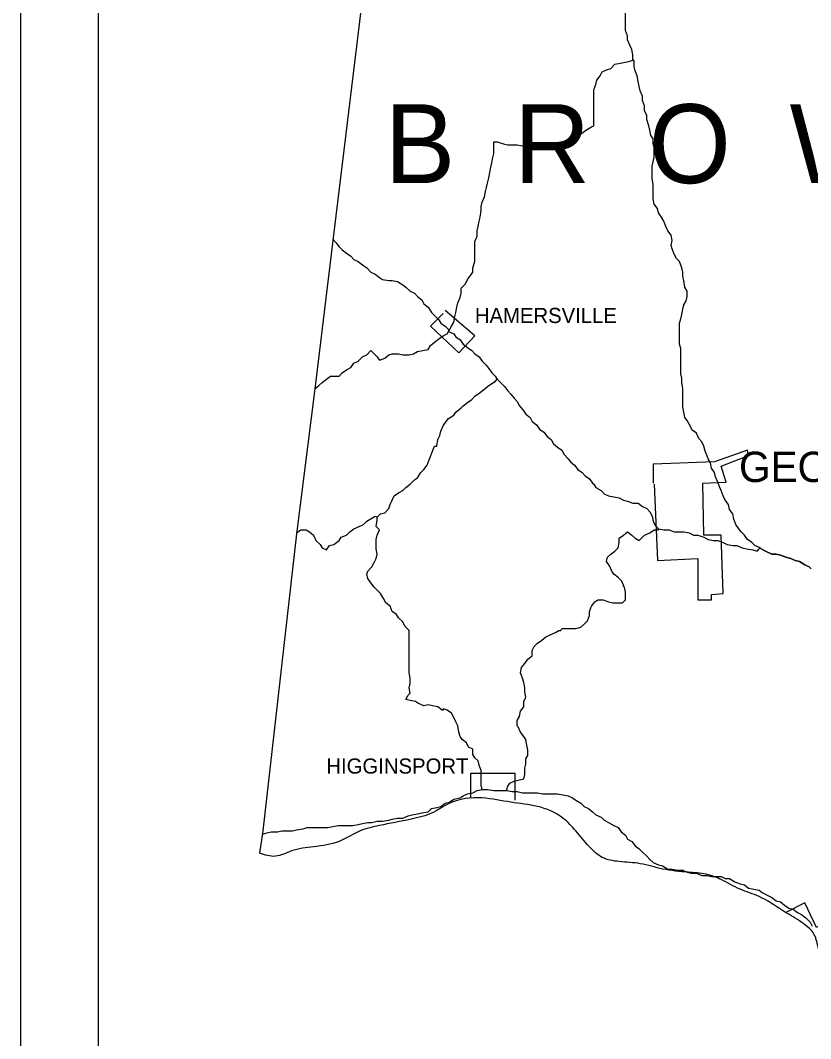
# Model space of a CAD drawing. Extents: x 0 to 34, y 0 to 22.
# Drawn here: x 2 to 3.016, y 16.334 to 17.643 of the extents above; entities that cross this region are included whole.
import ezdxf

# ---------------------------------------------------------------- set-up
doc = ezdxf.new("R2010")
doc.units = 0
for name, color, linetype in [('Default', 7, 'Continuous'), ('SH_Data', 7, 'Continuous'), ('TR_Turning_Path1', 7, 'Continuous')]:
    doc.layers.add(name, color=color, linetype=linetype)

msp = doc.modelspace()

# ---------------------------------------------------------------- linework, layer by layer
at = {"layer": 'Default'}
for points in [[(2.5542, 18.7551), (2.546, 18.6256), (2.5378, 18.5029), (2.5255, 18.387), (2.5105, 18.2684), (2.5078, 18.2343), (2.4914, 18.0952), (2.4737, 17.9548), (2.456, 17.8075), (2.4014, 17.3603), (2.3783, 17.1694), (2.3551, 16.9827), (2.3115, 16.6009), (2.3074, 16.5723)], [(2.7873, 17.5935), (2.7873, 17.5989), (2.7859, 17.6057), (2.7832, 17.6112), (2.7805, 17.618), (2.7805, 17.6235), (2.7778, 17.6303), (2.7778, 17.6371), (2.7778, 17.6439), (2.7778, 17.6507), (2.7778, 17.6562), (2.7791, 17.663), (2.7805, 17.6685), (2.7805, 17.6753), (2.7805, 17.6835), (2.7805, 17.6889), (2.7805, 17.6957), (2.7859, 17.7012), (2.7887, 17.7066), (2.7928, 17.7121), (2.7955, 17.7175), (2.7968, 17.7244), (2.7968, 17.7244)], [(2.7369, 17.5089), (2.7369, 17.5158), (2.7369, 17.5212), (2.7369, 17.528), (2.7369, 17.5348), (2.7369, 17.5403), (2.7369, 17.5471), (2.7369, 17.5539), (2.7396, 17.5607), (2.7409, 17.5662), (2.745, 17.5717), (2.7478, 17.5771), (2.7532, 17.5798), (2.7587, 17.5812), (2.7641, 17.5867), (2.7709, 17.588), (2.7778, 17.5894), (2.7832, 17.5907), (2.7873, 17.5921), (2.7873, 17.5935)], [(2.8105, 17.4953), (2.8091, 17.5021), (2.8077, 17.5076), (2.805, 17.5158), (2.805, 17.5212), (2.8023, 17.5267), (2.8023, 17.5335), (2.7996, 17.5403), (2.7996, 17.5458), (2.7968, 17.5526), (2.7955, 17.558), (2.7941, 17.5648), (2.7928, 17.5717), (2.79, 17.5785), (2.7887, 17.5839), (2.7887, 17.5907), (2.7873, 17.5935)], [(2.6005, 17.4339), (2.6019, 17.4408), (2.6032, 17.4476), (2.6046, 17.4544), (2.606, 17.4599), (2.6073, 17.4667), (2.6087, 17.4721), (2.6087, 17.4789), (2.6087, 17.4871), (2.6128, 17.4871), (2.621, 17.4844), (2.6264, 17.483), (2.6319, 17.483), (2.6387, 17.483), (2.6455, 17.4817), (2.6523, 17.4803), (2.6578, 17.4803), (2.6646, 17.4803), (2.6714, 17.4789), (2.6769, 17.4776), (2.6823, 17.4803), (2.6891, 17.483), (2.6946, 17.4871), (2.7, 17.4885), (2.7069, 17.4898), (2.7123, 17.4912), (2.7178, 17.4953), (2.7232, 17.4994), (2.7287, 17.5035), (2.7341, 17.5062), (2.7369, 17.5076), (2.7369, 17.5089)], [(2.8118, 17.4421), (2.8118, 17.4476), (2.8118, 17.4558), (2.8132, 17.4612), (2.8146, 17.4667), (2.8146, 17.4721), (2.8146, 17.4803), (2.8132, 17.4844), (2.8132, 17.4912), (2.8105, 17.4953)], [(2.5501, 17.2431), (2.5542, 17.2499), (2.5569, 17.2553), (2.5582, 17.2622), (2.5596, 17.2676), (2.561, 17.2744), (2.5623, 17.2799), (2.5651, 17.2867), (2.5664, 17.2922), (2.5664, 17.299), (2.5719, 17.3044), (2.5746, 17.3099), (2.5787, 17.3153), (2.5814, 17.3194), (2.5814, 17.3249), (2.5841, 17.3331), (2.5841, 17.3399), (2.5841, 17.3453), (2.5841, 17.3521), (2.5841, 17.359), (2.5869, 17.3658), (2.5869, 17.3726), (2.5882, 17.378), (2.5896, 17.3849), (2.591, 17.3903), (2.5923, 17.3985), (2.5923, 17.404), (2.5937, 17.4094), (2.5964, 17.4162), (2.5978, 17.423), (2.5991, 17.4285), (2.6005, 17.4339), (2.6005, 17.4339)], [(2.8568, 17.2894), (2.8568, 17.2949), (2.8541, 17.3003), (2.8527, 17.3085), (2.8514, 17.314), (2.8514, 17.3194), (2.85, 17.3249), (2.8473, 17.3331), (2.8432, 17.3371), (2.8405, 17.3426), (2.8377, 17.3494), (2.8364, 17.3535), (2.8377, 17.3603), (2.8364, 17.3671), (2.8323, 17.3726), (2.8296, 17.378), (2.8268, 17.3849), (2.8241, 17.3903), (2.82, 17.3958), (2.8187, 17.4012), (2.8146, 17.4067), (2.8132, 17.4135), (2.8132, 17.4203), (2.8132, 17.4258), (2.8132, 17.4326), (2.8118, 17.4394), (2.8118, 17.4421), (2.8118, 17.4421)], [(2.4014, 17.3617), (2.4055, 17.3576), (2.4096, 17.3521), (2.4137, 17.3481), (2.4192, 17.344), (2.4246, 17.3399), (2.4287, 17.3358), (2.4342, 17.3331), (2.4396, 17.329), (2.4451, 17.3249), (2.4505, 17.3194), (2.456, 17.3167), (2.4614, 17.3126), (2.4655, 17.3099), (2.4737, 17.3085), (2.4778, 17.3085), (2.4846, 17.3072), (2.4914, 17.3031), (2.4955, 17.3003), (2.501, 17.2949), (2.5064, 17.2922), (2.5105, 17.2881), (2.516, 17.284), (2.5187, 17.2785), (2.5242, 17.2744), (2.5282, 17.2676), (2.5323, 17.2635), (2.5378, 17.2581), (2.5405, 17.254), (2.546, 17.2499), (2.5501, 17.2458), (2.5501, 17.2431)], [(2.4014, 17.3617), (2.4055, 17.3576), (2.4096, 17.3521), (2.4137, 17.3481), (2.4192, 17.344), (2.4246, 17.3399), (2.4287, 17.3358), (2.4342, 17.3331), (2.4396, 17.329), (2.4451, 17.3249), (2.4505, 17.3194), (2.456, 17.3167), (2.4614, 17.3126), (2.4655, 17.3099), (2.4737, 17.3085), (2.4778, 17.3085), (2.4846, 17.3072), (2.4914, 17.3031), (2.4955, 17.3003), (2.501, 17.2949), (2.5064, 17.2922), (2.5105, 17.2881), (2.516, 17.284), (2.5187, 17.2785), (2.5242, 17.2744), (2.5282, 17.2676), (2.5323, 17.2635), (2.5378, 17.2581), (2.5405, 17.254), (2.546, 17.2499), (2.5501, 17.2458), (2.5501, 17.2431)], [(2.8487, 17.2076), (2.8487, 17.2131), (2.8487, 17.2213), (2.8473, 17.2267), (2.8473, 17.2335), (2.8473, 17.2403), (2.8473, 17.2458), (2.8473, 17.254), (2.8487, 17.2594), (2.85, 17.2649), (2.8514, 17.2717), (2.8527, 17.2772), (2.8555, 17.2826), (2.8568, 17.2881), (2.8568, 17.2894)], [(2.5432, 17.2662), (2.5269, 17.2499), (2.5637, 17.2158), (2.5841, 17.2376), (2.546, 17.2703)], [(2.4614, 17.2063), (2.4683, 17.209), (2.4737, 17.2131), (2.4778, 17.2144), (2.486, 17.2144), (2.4914, 17.2131), (2.4996, 17.2131), (2.5051, 17.2144), (2.5105, 17.2172), (2.5173, 17.2185), (2.5242, 17.2199), (2.5269, 17.2253), (2.5323, 17.2294), (2.5378, 17.2335), (2.5432, 17.2376), (2.5487, 17.2403), (2.5501, 17.2431), (2.5501, 17.2431)], [(2.5501, 17.2431), (2.5569, 17.2403), (2.5596, 17.2363), (2.5651, 17.2322), (2.5691, 17.2267), (2.5746, 17.2226), (2.5801, 17.2185), (2.5841, 17.2144), (2.5896, 17.2103), (2.5937, 17.2049), (2.5978, 17.2008), (2.6019, 17.1954), (2.606, 17.1899), (2.6101, 17.1858), (2.6128, 17.1817)], [(2.5501, 17.2431), (2.5569, 17.2403), (2.5596, 17.2363), (2.5651, 17.2322), (2.5691, 17.2267), (2.5746, 17.2226), (2.5801, 17.2185), (2.5841, 17.2144), (2.5896, 17.2103), (2.5937, 17.2049), (2.5978, 17.2008), (2.6019, 17.1954), (2.606, 17.1899), (2.6101, 17.1858), (2.6128, 17.1817)], [(2.3783, 17.1694), (2.3837, 17.1735), (2.3878, 17.1776), (2.3933, 17.1817), (2.3987, 17.1858), (2.4042, 17.1858), (2.4096, 17.1858), (2.4137, 17.1899), (2.4192, 17.194), (2.4246, 17.1967), (2.4287, 17.2022), (2.4342, 17.2049), (2.4396, 17.2103), (2.4451, 17.2131), (2.4505, 17.2185), (2.4546, 17.2144), (2.4587, 17.2103), (2.4614, 17.2063), (2.4614, 17.2063)], [(2.8514, 17.1572), (2.8514, 17.164), (2.8514, 17.1694), (2.85, 17.1776), (2.85, 17.1831), (2.8487, 17.1885), (2.8487, 17.1954), (2.8487, 17.2022), (2.8487, 17.2076)], [(2.5351, 17.0958), (2.5364, 17.104), (2.5392, 17.1095), (2.5405, 17.1149), (2.5432, 17.1217), (2.5473, 17.1272), (2.5501, 17.1313), (2.5569, 17.1354), (2.5596, 17.1395), (2.5664, 17.1449), (2.5691, 17.1476), (2.5746, 17.1517), (2.5801, 17.1558), (2.5841, 17.1599), (2.5896, 17.164), (2.5951, 17.1681), (2.6005, 17.1722), (2.606, 17.1763), (2.6101, 17.179), (2.6128, 17.1817)], [(2.6128, 17.1817), (2.6169, 17.1776), (2.6223, 17.1722), (2.6264, 17.1667), (2.6305, 17.1626), (2.6346, 17.1572), (2.6387, 17.1531), (2.6414, 17.1476), (2.6469, 17.1408), (2.6496, 17.1367), (2.655, 17.1326), (2.6578, 17.1272), (2.6632, 17.1231), (2.6673, 17.1176), (2.6728, 17.1135), (2.6769, 17.1081), (2.6823, 17.104), (2.685, 17.0985), (2.6905, 17.0945), (2.6959, 17.0904), (2.6987, 17.0849), (2.7041, 17.0795), (2.7069, 17.0754), (2.7123, 17.0713), (2.7164, 17.0658), (2.7219, 17.0617), (2.7259, 17.0576), (2.7314, 17.0536), (2.7355, 17.0481), (2.7369, 17.0467)], [(2.6128, 17.1817), (2.6169, 17.1776), (2.6223, 17.1722), (2.6264, 17.1667), (2.6305, 17.1626), (2.6346, 17.1572), (2.6387, 17.1531), (2.6414, 17.1476), (2.6469, 17.1408), (2.6496, 17.1367), (2.655, 17.1326), (2.6578, 17.1272), (2.6632, 17.1231), (2.6673, 17.1176), (2.6728, 17.1135), (2.6769, 17.1081), (2.6823, 17.104), (2.685, 17.0985), (2.6905, 17.0945), (2.6959, 17.0904), (2.6987, 17.0849), (2.7041, 17.0795), (2.7069, 17.0754), (2.7123, 17.0713), (2.7164, 17.0658), (2.7219, 17.0617), (2.7259, 17.0576), (2.7314, 17.0536), (2.7355, 17.0481), (2.7369, 17.0467)], [(2.88, 17.089), (2.8786, 17.0958), (2.8759, 17.1013), (2.8718, 17.1054), (2.8691, 17.1122), (2.8636, 17.1163), (2.8609, 17.1217), (2.8568, 17.1285), (2.8541, 17.1326), (2.8527, 17.1395), (2.8514, 17.1463), (2.8514, 17.1517), (2.8514, 17.1572)], [(2.4587, 17.0045), (2.4628, 17.0086), (2.4683, 17.0099), (2.4737, 17.0154), (2.4751, 17.0208), (2.4778, 17.0263), (2.4805, 17.0317), (2.486, 17.0358), (2.4914, 17.0386), (2.4955, 17.0426), (2.501, 17.0467), (2.5064, 17.0522), (2.5105, 17.0549), (2.5146, 17.0617), (2.5187, 17.0658), (2.5228, 17.0713), (2.5255, 17.0781), (2.5269, 17.0822), (2.5296, 17.089), (2.5323, 17.0958), (2.5351, 17.0958)], [(2.8146, 17.0467), (2.8187, 16.9486), (2.8705, 16.9513), (2.8705, 16.8981), (2.8882, 16.8981), (2.8882, 16.9049), (2.9032, 16.9063), (2.9005, 16.9813), (2.8786, 16.9813), (2.8773, 17.0481), (2.9073, 17.0495), (2.9005, 17.0699), (2.9359, 17.0836), (2.9345, 17.0904), (2.8923, 17.0754), (2.8132, 17.0726), (2.8132, 17.0481)], [(2.9509, 16.9649), (2.9441, 16.9677), (2.94, 16.9718), (2.9345, 16.9758), (2.9305, 16.9813), (2.9264, 16.9854), (2.9236, 16.9895), (2.9195, 16.9949), (2.9168, 17.0017), (2.9155, 17.0086), (2.9114, 17.014), (2.91, 17.0208), (2.9059, 17.0263), (2.9032, 17.0317), (2.9005, 17.0386), (2.8991, 17.0426), (2.8964, 17.0495), (2.8936, 17.0563), (2.8923, 17.0617), (2.8882, 17.0672), (2.8868, 17.074), (2.8841, 17.0795), (2.8814, 17.0863), (2.88, 17.089)], [(2.7369, 17.0467), (2.7396, 17.0426), (2.7464, 17.0386), (2.7505, 17.0345), (2.7559, 17.0317), (2.7628, 17.0304), (2.7696, 17.029), (2.775, 17.0263), (2.7805, 17.0249), (2.7873, 17.0222), (2.7941, 17.0222), (2.7996, 17.0181), (2.805, 17.0154), (2.8091, 17.0113), (2.8118, 17.0058), (2.8132, 16.999), (2.8159, 16.9936), (2.82, 16.9895), (2.82, 16.9895)], [(2.7369, 17.0467), (2.7396, 17.0426), (2.7464, 17.0386), (2.7505, 17.0345), (2.7559, 17.0317), (2.7628, 17.0304), (2.7696, 17.029), (2.775, 17.0263), (2.7805, 17.0249), (2.7873, 17.0222), (2.7941, 17.0222), (2.7996, 17.0181), (2.805, 17.0154), (2.8091, 17.0113), (2.8118, 17.0058), (2.8132, 16.999), (2.8159, 16.9936), (2.82, 16.9895), (2.82, 16.9895)], [(2.3551, 16.984), (2.3605, 16.9881), (2.3674, 16.9881), (2.3715, 16.9854), (2.3769, 16.9813), (2.3796, 16.9745), (2.3851, 16.969), (2.3878, 16.9649), (2.3933, 16.9622), (2.3974, 16.9677), (2.4028, 16.969), (2.4096, 16.9745), (2.4124, 16.9786), (2.4192, 16.9813), (2.4233, 16.9854), (2.4287, 16.9895), (2.4355, 16.9922), (2.441, 16.9949), (2.4451, 16.999), (2.4519, 17.0031), (2.456, 17.0058), (2.4587, 17.0045)], [(2.4996, 16.8586), (2.4942, 16.864), (2.4914, 16.8695), (2.486, 16.8749), (2.4833, 16.879), (2.4778, 16.8831), (2.4751, 16.8899), (2.4696, 16.894), (2.4669, 16.8995), (2.4628, 16.9063), (2.4587, 16.9104), (2.4546, 16.9145), (2.4505, 16.9199), (2.4464, 16.9254), (2.4451, 16.9308), (2.4464, 16.9349), (2.4519, 16.9404), (2.4546, 16.9458), (2.4573, 16.9513), (2.4587, 16.9568), (2.4573, 16.9636), (2.4573, 16.969), (2.4573, 16.9758), (2.4587, 16.9813), (2.4614, 16.9881), (2.4573, 16.9922), (2.4587, 17.0004), (2.4587, 17.0017), (2.4587, 17.0045)], [(2.775, 16.9172), (2.7723, 16.9227), (2.7682, 16.9268), (2.7628, 16.9308), (2.76, 16.9349), (2.7573, 16.9418), (2.7532, 16.9472), (2.7546, 16.9527), (2.7587, 16.9568), (2.7641, 16.9608), (2.7682, 16.9649), (2.7696, 16.9718), (2.7696, 16.9772), (2.775, 16.9813), (2.7805, 16.9854), (2.7859, 16.9813), (2.79, 16.9772), (2.7955, 16.9745), (2.7996, 16.9786), (2.8023, 16.9813), (2.8091, 16.984), (2.8146, 16.9881), (2.82, 16.9881), (2.82, 16.9895)], [(2.82, 16.9895), (2.8268, 16.9881), (2.8337, 16.9881), (2.8405, 16.9854), (2.8459, 16.9854), (2.8527, 16.9854), (2.8596, 16.984), (2.865, 16.9813), (2.8705, 16.9813), (2.8786, 16.9786), (2.8841, 16.9758), (2.8909, 16.9745), (2.8964, 16.9745), (2.9032, 16.9718), (2.9086, 16.969), (2.9155, 16.9677), (2.9209, 16.9677), (2.9277, 16.9649), (2.9332, 16.9636), (2.9414, 16.9622), (2.9468, 16.9608), (2.9495, 16.9636), (2.9509, 16.9649)], [(2.82, 16.9895), (2.8268, 16.9881), (2.8337, 16.9881), (2.8405, 16.9854), (2.8459, 16.9854), (2.8527, 16.9854), (2.8596, 16.984), (2.865, 16.9813), (2.8705, 16.9813), (2.8786, 16.9786), (2.8841, 16.9758), (2.8909, 16.9745), (2.8964, 16.9745), (2.9032, 16.9718), (2.9086, 16.969), (2.9155, 16.9677), (2.9209, 16.9677), (2.9277, 16.9649), (2.9332, 16.9636), (2.9414, 16.9622), (2.9468, 16.9608), (2.9495, 16.9636), (2.9509, 16.9649)], [(2.9509, 16.9649), (2.9523, 16.9636), (2.9577, 16.9608), (2.9659, 16.9568), (2.9714, 16.9568), (2.9768, 16.9554), (2.9836, 16.9527), (2.9904, 16.9513), (2.9959, 16.9486), (3.0014, 16.9472), (3.0082, 16.9431), (3.0136, 16.9404)], [(2.9509, 16.9649), (2.9523, 16.9636), (2.9577, 16.9608), (2.9659, 16.9568), (2.9714, 16.9568), (2.9768, 16.9554), (2.9836, 16.9527), (2.9904, 16.9513), (2.9959, 16.9486), (3.0014, 16.9472), (3.0082, 16.9431), (3.0136, 16.9404)], [(3.0136, 16.9404), (3.0082, 16.9431), (3.0014, 16.9472), (2.9959, 16.9486), (2.9904, 16.9513), (2.9836, 16.9527), (2.9768, 16.9554), (2.9714, 16.9568), (2.9659, 16.9568), (2.9577, 16.9608), (2.9523, 16.9636), (2.9509, 16.9649)], [(3.0164, 16.9377), (3.015, 16.939), (3.0136, 16.9404)], [(2.6959, 16.8613), (2.7014, 16.8613), (2.7069, 16.8613), (2.7137, 16.8613), (2.7205, 16.8627), (2.7246, 16.8668), (2.7287, 16.8709), (2.7314, 16.8777), (2.7314, 16.8831), (2.7341, 16.8899), (2.7382, 16.8954), (2.7423, 16.8981), (2.7491, 16.8981), (2.7559, 16.8954), (2.7614, 16.894), (2.7682, 16.894), (2.7737, 16.894), (2.7778, 16.8981), (2.7778, 16.9022), (2.7778, 16.9077), (2.7764, 16.9145), (2.775, 16.9158), (2.775, 16.9172)], [(2.5419, 16.7563), (2.5364, 16.7604), (2.5296, 16.7618), (2.5242, 16.7631), (2.5187, 16.7618), (2.5119, 16.7645), (2.5078, 16.7672), (2.501, 16.7686), (2.4955, 16.77), (2.4983, 16.7754), (2.501, 16.7781), (2.4996, 16.785), (2.501, 16.7904), (2.501, 16.7972), (2.4996, 16.804), (2.4996, 16.8095), (2.4996, 16.8177), (2.4996, 16.8218), (2.4996, 16.8286), (2.4996, 16.8368), (2.4996, 16.8422), (2.4996, 16.8504), (2.4996, 16.8572), (2.4996, 16.8572), (2.4996, 16.8586)], [(2.6387, 16.7359), (2.6387, 16.7427), (2.6414, 16.7481), (2.6428, 16.755), (2.6469, 16.7604), (2.6469, 16.7672), (2.6496, 16.7727), (2.6482, 16.7795), (2.6482, 16.785), (2.6469, 16.7918), (2.6455, 16.7972), (2.6428, 16.804), (2.6441, 16.8109), (2.6482, 16.8163), (2.6523, 16.8218), (2.6578, 16.8259), (2.6578, 16.8327), (2.6605, 16.8381), (2.6646, 16.8422), (2.67, 16.8463), (2.6755, 16.8504), (2.6809, 16.8531), (2.6878, 16.8559), (2.6919, 16.8586), (2.6946, 16.8586), (2.6959, 16.8613)], [(2.5937, 16.6541), (2.5923, 16.6595), (2.5923, 16.6663), (2.5923, 16.6732), (2.5923, 16.6786), (2.5896, 16.6854), (2.5882, 16.6909), (2.5841, 16.695), (2.5814, 16.6991), (2.5814, 16.7059), (2.576, 16.7086), (2.5732, 16.7141), (2.5678, 16.7182), (2.5651, 16.7222), (2.5637, 16.7277), (2.5623, 16.7359), (2.5596, 16.7413), (2.5569, 16.7468), (2.5542, 16.7522), (2.5487, 16.7563), (2.5432, 16.7577), (2.5432, 16.7563), (2.5419, 16.7563)], [(2.625, 16.6527), (2.6264, 16.6582), (2.6291, 16.6623), (2.6346, 16.665), (2.6414, 16.6663), (2.6469, 16.6677), (2.6482, 16.6732), (2.6482, 16.6813), (2.6496, 16.6868), (2.6496, 16.6936), (2.6523, 16.6977), (2.6523, 16.7045), (2.651, 16.7113), (2.6496, 16.7182), (2.6469, 16.7222), (2.6428, 16.7277), (2.64, 16.7345), (2.6387, 16.7359)], [(2.636, 16.6404), (2.636, 16.6745), (2.5787, 16.6745), (2.5787, 16.6432)], [(2.3115, 16.5968), (2.3169, 16.5982), (2.3224, 16.5995), (2.3306, 16.5995), (2.336, 16.6009), (2.3442, 16.6009), (2.3496, 16.6009), (2.3551, 16.6023), (2.3633, 16.6036), (2.3687, 16.605), (2.3769, 16.605), (2.3824, 16.605), (2.3878, 16.605), (2.3946, 16.605), (2.4014, 16.6064), (2.4083, 16.6077), (2.4137, 16.6077), (2.4205, 16.6077), (2.4274, 16.6077), (2.4342, 16.6091), (2.4396, 16.6104), (2.4464, 16.6118), (2.4519, 16.6118), (2.4587, 16.6132), (2.4655, 16.6132), (2.4737, 16.6145), (2.4778, 16.6159), (2.4846, 16.6173), (2.4914, 16.6173), (2.4983, 16.62), (2.5037, 16.6214), (2.5105, 16.6227), (2.516, 16.6241), (2.5242, 16.6254), (2.5282, 16.6295), (2.5351, 16.6309), (2.5405, 16.6323), (2.546, 16.6363), (2.5514, 16.6377), (2.5569, 16.6418), (2.5651, 16.6432), (2.5691, 16.6459), (2.5746, 16.6486), (2.5814, 16.65), (2.5869, 16.6527), (2.5937, 16.6541), (2.5937, 16.6541)], [(2.5937, 16.6541), (2.6005, 16.6541), (2.6087, 16.6527), (2.6155, 16.6527), (2.621, 16.6527), (2.625, 16.6527)], [(2.625, 16.6527), (2.6319, 16.6513), (2.6387, 16.6513), (2.6455, 16.65), (2.6523, 16.65), (2.6578, 16.65), (2.6646, 16.65), (2.6714, 16.6486), (2.6769, 16.6486), (2.6837, 16.6486), (2.6905, 16.6486), (2.6973, 16.6473), (2.7041, 16.6459), (2.7096, 16.6432), (2.7137, 16.6404), (2.7205, 16.6363), (2.7246, 16.6323), (2.73, 16.6295), (2.7355, 16.6254), (2.7396, 16.6214), (2.7464, 16.6186), (2.7464, 16.6186)], [(2.7464, 16.6186), (2.7505, 16.6145), (2.7559, 16.6118), (2.7628, 16.6077), (2.7682, 16.605), (2.7723, 16.5995), (2.7778, 16.5954), (2.7805, 16.59), (2.7859, 16.5873), (2.79, 16.5818), (2.7955, 16.5777), (2.7996, 16.5736), (2.805, 16.5682), (2.8091, 16.5641), (2.8132, 16.56), (2.82, 16.5573), (2.8255, 16.5559), (2.8323, 16.5518), (2.8377, 16.5518), (2.8446, 16.5505), (2.8514, 16.5505), (2.8568, 16.5477), (2.8623, 16.5464), (2.8691, 16.5464), (2.8759, 16.5436), (2.8827, 16.5436), (2.8882, 16.5423), (2.895, 16.5423), (2.9005, 16.5423), (2.9059, 16.5395)], [(2.9059, 16.5395), (2.9114, 16.5395), (2.9182, 16.5355), (2.925, 16.5327), (2.9305, 16.5314), (2.9359, 16.5273), (2.9427, 16.5259), (2.9495, 16.5245), (2.9536, 16.5218), (2.9605, 16.5177), (2.9659, 16.515), (2.9714, 16.5109), (2.9768, 16.5096), (2.9823, 16.5055), (2.9877, 16.5014), (2.9932, 16.5), (2.9986, 16.4959), (3.0041, 16.4932), (3.0095, 16.4891), (3.015, 16.4836), (3.0177, 16.4782)], [(3.0532, 16.3459), (3.1077, 16.3732), (3.0641, 16.4646), (3.0913, 16.4768), (3.0804, 16.5055), (3.0232, 16.4768), (3.0082, 16.5082), (2.9836, 16.4959)]]:
    msp.add_lwpolyline(points, dxfattribs=at)
msp.add_spline([(3.5304, 15.9587), (3.5099, 15.9587), (3.5031, 15.9669), (3.4895, 15.9696), (3.484, 15.9792), (3.4758, 15.986), (3.4622, 15.986), (3.4404, 15.9942), (3.4186, 15.9915), (3.3858, 15.9983), (3.3572, 16.0078), (3.3299, 16.0119), (3.3136, 16.0187), (3.2999, 16.0283), (3.2931, 16.0405), (3.2795, 16.0637), (3.2781, 16.0896), (3.274, 16.1169), (3.2672, 16.1387), (3.2645, 16.1701), (3.2577, 16.2041), (3.2468, 16.2246), (3.2304, 16.2396), (3.2113, 16.2532), (3.195, 16.26), (3.1704, 16.2682), (3.1404, 16.271), (3.1172, 16.2791), (3.1036, 16.2887), (3.0845, 16.3023), (3.0682, 16.3132), (3.0545, 16.3296), (3.0477, 16.3514), (3.0477, 16.3718), (3.0409, 16.3923), (3.0341, 16.4264), (3.0259, 16.4496), (3.0204, 16.4673), (3.0014, 16.485), (2.9795, 16.4986), (2.9495, 16.5164), (2.925, 16.5259), (2.9005, 16.5382), (2.8814, 16.545), (2.8582, 16.5477), (2.8255, 16.5518), (2.7968, 16.5586), (2.7696, 16.5614), (2.7478, 16.5668), (2.7314, 16.5804), (2.7137, 16.6009), (2.6973, 16.6173), (2.6646, 16.6323), (2.6305, 16.6377), (2.5937, 16.6432), (2.5514, 16.6363), (2.5296, 16.6241), (2.5023, 16.6159), (2.4614, 16.6077), (2.4369, 16.6009), (2.4096, 16.5873), (2.3769, 16.5804), (2.3483, 16.575), (2.3278, 16.5682), (2.3074, 16.5723)], degree=3, dxfattribs=at)
at = {"layer": 'SH_Data'}
for p, q in [((2, 21), (2, 14)), ((2.1, 20.9), (2.1, 14.1))]:
    msp.add_line(p, q, dxfattribs=at)

# ---------------------------------------------------------------- texts
at = {"layer": 'Default'}
for s, height, p in [('HAMERSVILLE', 0.019502, (2.5841, 17.254)), ('GEORGETOWN', 0.039, (2.9236, 17.0495)), ('HIGGINSPORT', 0.019502, (2.3933, 16.6745))]:
    msp.add_text(s, height=height, dxfattribs=at).set_placement(p)
at = {"layer": 'TR_Turning_Path1'}
msp.add_text('B  R  O  W  N', height=0.101489, dxfattribs=at).set_placement((2.4683, 17.4339))

doc.saveas('drawing.dxf')
